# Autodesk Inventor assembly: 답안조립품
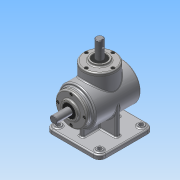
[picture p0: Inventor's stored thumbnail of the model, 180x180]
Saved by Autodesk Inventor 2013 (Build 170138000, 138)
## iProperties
Created: 2015-07
Part Number: 답안조립품
Document SubType Name: Assembly
Designer: Administrator
Author: Administrator
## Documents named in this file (14)
- C:\Users\Administrator\Desktop\450706V1025\답안조립품.iam
- C:\Users\Administrator\Desktop\450706V1025\본체.ipt
- C:\Users\Administrator\Desktop\450706V1025\커버.ipt
- C:\Users\Administrator\Desktop\450706V1025\서브 축.ipt
- 서브 축.ipt
- C:\Users\Administrator\Desktop\450706V1025\베어링 6203.ipt
- C:\Users\Administrator\Desktop\450706V1025\메인 축.ipt
- 메인 축.ipt
- C:\Users\Administrator\Desktop\450706V1025\M4.ipt
- C:\Users\Administrator\Desktop\450706V1025\키 4x4.ipt
- C:\Users\Administrator\Desktop\450706V1025\키 5x5.ipt
- C:\Users\Administrator\Desktop\450706V1025\오일실.ipt
- C:\Users\Administrator\Desktop\450706V1025\메인 베벨기어.ipt
- C:\Users\Administrator\Desktop\450706V1025\서브 베벨기어.ipt
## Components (8 placed, 1 different names)
1. M4:1
2. M4:3
3. M4:4
4. M4:5
5. M4:2
6. M4:6
7. M4:7
8. M4:8
